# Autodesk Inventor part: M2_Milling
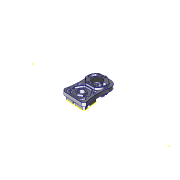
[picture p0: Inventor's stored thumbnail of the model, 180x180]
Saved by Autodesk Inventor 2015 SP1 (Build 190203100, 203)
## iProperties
Created: 2015-04
Part Number: M2_Milling
Material: Aço
Document SubType Name: Modeling
Designer: Andrew Almeida
Density: 7.85 g/cm^3
Appearance: Placa
Title: C:/Users/Andrew Almeida/Documents/Projeto WS2015/WS2015 CAD Data ANLAS/07/#07 - CNC Milling/01 - 3D Models/M2_Milling.stp
Creation Date: 2015-04-23
Sending System: Autodesk Translation Framework v4.0.0.5211
Preprocessor: ST-DEVELOPER v16.1
Author: Andrew Almeida
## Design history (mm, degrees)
node "M2_Milling1"
feature "Rosca1" dims "d0" = 10, "d1" = 0
feature "Rosca2" dims "d2" = 10, "d3" = 0
feature "Rosca3" dims "d4" = 10, "d5" = 0
feature "Rosca4" dims "d6" = 10, "d7" = 0
feature "Rosca5" dims "d8" = 10, "d9" = 0
feature "Rosca6" dims "d10" = 10, "d11" = 0
feature "Rosca7" dims "d12" = 20, "d13" = 0
feature "Rosca8" dims "d14" = 10, "d15" = 0
feature "Rosca9" dims "d16" = 10, "d17" = 0
feature "Rosca10" dims "d18" = 10, "d19" = 0
sketch "Esboço2"
  geometry: L1 (4.188, 0)-(4.188, 22); L2 (4.188, 22)-(3.447, 22); L3 (3.447, 22)-(3.447, 0); L4 (3.447, 0)-(4.188, 0); L5 (0, -10.409)-(0, 54.818) reference
  constraints: 8 end point
revolve "Revolução1" sketch "Esboço2" stored, may be unused: angle "d29" = 0 deg
sketch "Esboço1"
  geometry: L1 (-0.583, -0.051)-(-0.5, -0.051); L2 (0.083, -0.691)-(0, -0.851); L3 (-1, -0.851)-(-1.083, -0.691); L4 (-0.417, -0.051)-(-0.5, 0.109); L5 (-0.5, 0.109)-(-0.583, -0.051); L6 (-1, -0.851)-(-0.917, -0.691); L7 (-0.417, -0.051)-(-0.083, -0.691); L8 (-1.083, -0.691)-(-0.917, -0.691); L9 (0.083, -0.691)-(-0.083, -0.691); L10 (-1, -0.851)-(-1, -0.691); L11 (0, -0.851)-(0, -0.691); L12 (-0.5, 0.109)-(-0.5, 0); L13 (-1, -0.742)-(0, -0.742); L14 (-0.083, -0.691)-(0, -0.851); L15 (-0.917, -0.691)-(-0.583, -0.051); L16 (0, 0)-(0, 0.018); L17 (0, 0.018)-(0, 0); L18 (0, 0)-(0.033, 0); L19 (-0.5, 0)-(-0.5, -0.051); L20 (-0.5, -0.051)-(-0.417, -0.051); A1 r 0.094 centre (-1, -0.648) between (-1.083, -0.691) and (-1, -0.742); A2 r 0.094 centre (-1, -0.648) between (-1, -0.742) and (-0.917, -0.691); A3 r 0.094 centre (0, -0.648) between (-0.083, -0.691) and (0, -0.742); A4 r 0.094 centre (0, -0.648) between (0, -0.742) and (0.083, -0.691); A5 r 0.094 centre (-0.5, -0.094) between (-0.5, 0) and (-0.583, -0.051); A6 r 0.094 centre (-0.5, -0.094) between (-0.417, -0.051) and (-0.5, 0)
  constraints: 40 end point, 12 point on circle, 10 parallel, 8 tangent, 6 centre point, 6 collinear, 2 midpoint, 2 point on line, 1 horizontal, 1 perpendicular, 3 other
  dimensions: "d20" = 55 deg angle of L7 L15 (= d27); "d21" = 0.16008 distance of L4.end L1.end (= 0.160083 x Esboço1_Pitch); "d22" = 0.16008 distance of L2.end L11.end (= 0.160083 x Esboço1_Pitch); "Esboço1_ThreadOffset" = 0 distance between parallel lines of L16 L11; "Esboço1_MajorRadius" = 0.74146 distance from line of L13 L16.start; "d25" = 1 distance from line of L2.end L10 (= Esboço1_Pitch); "Esboço1_MinorRadius" = 0 distance edge to line of A6 L18 (derived)
feature "Espiral1" sketch "Esboço1" pitch "d30" = 1.5015; turns "d32" = 1; dims "d31" = 25, "d33" = 0, angle "d34" = 0 deg, angle "d35" = 0 deg, "d36" = 0, "d37" = 0
sketch "Esboço4"
  geometry: L1 (4.188, 0)-(4.188, 22); L2 (4.188, 22)-(3.447, 22); L3 (3.447, 22)-(3.447, 0); L4 (3.447, 0)-(4.188, 0); L5 (0, -10.409)-(0, 54.818) reference
  constraints: 8 end point
revolve "Revolução2" sketch "Esboço4" stored, may be unused: angle "d47" = 0 deg
sketch "Esboço3"
  geometry: L1 (-0.583, -0.051)-(-0.5, -0.051); L2 (0.083, -0.691)-(0, -0.851); L3 (-1, -0.851)-(-1.083, -0.691); L4 (-0.417, -0.051)-(-0.5, 0.109); L5 (-0.5, 0.109)-(-0.583, -0.051); L6 (-1, -0.851)-(-0.917, -0.691); L7 (-0.417, -0.051)-(-0.083, -0.691); L8 (-1.083, -0.691)-(-0.917, -0.691); L9 (0.083, -0.691)-(-0.083, -0.691); L10 (-1, -0.851)-(-1, -0.691); L11 (0, -0.851)-(0, -0.691); L12 (-0.5, 0.109)-(-0.5, 0); L13 (-1, -0.742)-(0, -0.742); L14 (-0.083, -0.691)-(0, -0.851); L15 (-0.917, -0.691)-(-0.583, -0.051); L16 (0, 0)-(0, 0.018); L17 (0, 0.018)-(0, 0); L18 (0, 0)-(0.033, 0); L19 (-0.5, 0)-(-0.5, -0.051); L20 (-0.5, -0.051)-(-0.417, -0.051); A1 r 0.094 centre (-1, -0.648) between (-1.083, -0.691) and (-1, -0.742); A2 r 0.094 centre (-1, -0.648) between (-1, -0.742) and (-0.917, -0.691); A3 r 0.094 centre (0, -0.648) between (-0.083, -0.691) and (0, -0.742); A4 r 0.094 centre (0, -0.648) between (0, -0.742) and (0.083, -0.691); A5 r 0.094 centre (-0.5, -0.094) between (-0.5, 0) and (-0.583, -0.051); A6 r 0.094 centre (-0.5, -0.094) between (-0.417, -0.051) and (-0.5, 0)
  constraints: 40 end point, 12 point on circle, 10 parallel, 8 tangent, 6 centre point, 6 collinear, 2 midpoint, 2 point on line, 1 horizontal, 1 perpendicular, 3 other
  dimensions: "d38" = 55 deg angle of L7 L15 (= d45); "d39" = 0.16008 distance of L4.end L1.end (= 0.160083 x Esboço3_Pitch); "d40" = 0.16008 distance of L2.end L11.end (= 0.160083 x Esboço3_Pitch); "Esboço3_ThreadOffset" = 0 distance between parallel lines of L16 L11; "Esboço3_MajorRadius" = 0.74146 distance from line of L13 L16.start; "d43" = 1 distance from line of L2.end L10 (= Esboço3_Pitch); "Esboço3_MinorRadius" = 0 distance edge to line of A6 L18 (derived)
feature "Espiral2" sketch "Esboço3" pitch "d48" = 1.5015; turns "d50" = 1; dims "d49" = 25, "d51" = 0, angle "d52" = 0 deg, angle "d53" = 0 deg, "d54" = 0, "d55" = 0
sketch "Esboço6"
  geometry: L1 (4.188, 0)-(4.188, 22); L2 (4.188, 22)-(3.447, 22); L3 (3.447, 22)-(3.447, 0); L4 (3.447, 0)-(4.188, 0); L5 (0, -10.409)-(0, 54.818) reference
  constraints: 8 end point
revolve "Revolução3" sketch "Esboço6" stored, may be unused: angle "d65" = 0 deg
sketch "Esboço5"
  geometry: L1 (-0.583, -0.051)-(-0.5, -0.051); L2 (0.083, -0.691)-(0, -0.851); L3 (-1, -0.851)-(-1.083, -0.691); L4 (-0.417, -0.051)-(-0.5, 0.109); L5 (-0.5, 0.109)-(-0.583, -0.051); L6 (-1, -0.851)-(-0.917, -0.691); L7 (-0.417, -0.051)-(-0.083, -0.691); L8 (-1.083, -0.691)-(-0.917, -0.691); L9 (0.083, -0.691)-(-0.083, -0.691); L10 (-1, -0.851)-(-1, -0.691); L11 (0, -0.851)-(0, -0.691); L12 (-0.5, 0.109)-(-0.5, 0); L13 (-1, -0.742)-(0, -0.742); L14 (-0.083, -0.691)-(0, -0.851); L15 (-0.917, -0.691)-(-0.583, -0.051); L16 (0, 0)-(0, 0.018); L17 (0, 0.018)-(0, 0); L18 (0, 0)-(0.033, 0); L19 (-0.5, 0)-(-0.5, -0.051); L20 (-0.5, -0.051)-(-0.417, -0.051); A1 r 0.094 centre (-1, -0.648) between (-1.083, -0.691) and (-1, -0.742); A2 r 0.094 centre (-1, -0.648) between (-1, -0.742) and (-0.917, -0.691); A3 r 0.094 centre (0, -0.648) between (-0.083, -0.691) and (0, -0.742); A4 r 0.094 centre (0, -0.648) between (0, -0.742) and (0.083, -0.691); A5 r 0.094 centre (-0.5, -0.094) between (-0.5, 0) and (-0.583, -0.051); A6 r 0.094 centre (-0.5, -0.094) between (-0.417, -0.051) and (-0.5, 0)
  constraints: 40 end point, 12 point on circle, 10 parallel, 8 tangent, 6 centre point, 6 collinear, 2 midpoint, 2 point on line, 1 horizontal, 1 perpendicular, 3 other
  dimensions: "d56" = 55 deg angle of L7 L15 (= d63); "d57" = 0.16008 distance of L4.end L1.end (= 0.160083 x Esboço5_Pitch); "d58" = 0.16008 distance of L2.end L11.end (= 0.160083 x Esboço5_Pitch); "Esboço5_ThreadOffset" = 0 distance between parallel lines of L16 L11; "Esboço5_MajorRadius" = 0.74146 distance from line of L13 L16.start; "d61" = 1 distance from line of L2.end L10 (= Esboço5_Pitch); "Esboço5_MinorRadius" = 0 distance edge to line of A6 L18 (derived)
feature "Espiral3" sketch "Esboço5" pitch "d66" = 1.5015; turns "d68" = 1; dims "d67" = 25, "d69" = 0, angle "d70" = 0 deg, angle "d71" = 0 deg, "d72" = 0, "d73" = 0
sketch "Esboço8"
  geometry: L1 (4.188, 0)-(4.188, 22); L2 (4.188, 22)-(3.447, 22); L3 (3.447, 22)-(3.447, 0); L4 (3.447, 0)-(4.188, 0); L5 (0, -10.409)-(0, 54.818) reference
  constraints: 8 end point
revolve "Revolução4" sketch "Esboço8" stored, may be unused: angle "d83" = 0 deg
sketch "Esboço7"
  geometry: L1 (-0.583, -0.051)-(-0.5, -0.051); L2 (0.083, -0.691)-(0, -0.851); L3 (-1, -0.851)-(-1.083, -0.691); L4 (-0.417, -0.051)-(-0.5, 0.109); L5 (-0.5, 0.109)-(-0.583, -0.051); L6 (-1, -0.851)-(-0.917, -0.691); L7 (-0.417, -0.051)-(-0.083, -0.691); L8 (-1.083, -0.691)-(-0.917, -0.691); L9 (0.083, -0.691)-(-0.083, -0.691); L10 (-1, -0.851)-(-1, -0.691); L11 (0, -0.851)-(0, -0.691); L12 (-0.5, 0.109)-(-0.5, 0); L13 (-1, -0.742)-(0, -0.742); L14 (-0.083, -0.691)-(0, -0.851); L15 (-0.917, -0.691)-(-0.583, -0.051); L16 (0, 0)-(0, 0.018); L17 (0, 0.018)-(0, 0); L18 (0, 0)-(0.033, 0); L19 (-0.5, 0)-(-0.5, -0.051); L20 (-0.5, -0.051)-(-0.417, -0.051); A1 r 0.094 centre (-1, -0.648) between (-1.083, -0.691) and (-1, -0.742); A2 r 0.094 centre (-1, -0.648) between (-1, -0.742) and (-0.917, -0.691); A3 r 0.094 centre (0, -0.648) between (-0.083, -0.691) and (0, -0.742); A4 r 0.094 centre (0, -0.648) between (0, -0.742) and (0.083, -0.691); A5 r 0.094 centre (-0.5, -0.094) between (-0.5, 0) and (-0.583, -0.051); A6 r 0.094 centre (-0.5, -0.094) between (-0.417, -0.051) and (-0.5, 0)
  constraints: 40 end point, 12 point on circle, 10 parallel, 8 tangent, 6 centre point, 6 collinear, 2 midpoint, 2 point on line, 1 horizontal, 1 perpendicular, 3 other
  dimensions: "d74" = 55 deg angle of L7 L15 (= d81); "d75" = 0.16008 distance of L4.end L1.end (= 0.160083 x Esboço7_Pitch); "d76" = 0.16008 distance of L2.end L11.end (= 0.160083 x Esboço7_Pitch); "Esboço7_ThreadOffset" = 0 distance between parallel lines of L16 L11; "Esboço7_MajorRadius" = 0.74146 distance from line of L13 L16.start; "d79" = 1 distance from line of L2.end L10 (= Esboço7_Pitch); "Esboço7_MinorRadius" = 0 distance edge to line of A6 L18 (derived)
feature "Espiral4" sketch "Esboço7" pitch "d84" = 1.5015; turns "d86" = 1; dims "d85" = 25, "d87" = 0, angle "d88" = 0 deg, angle "d89" = 0 deg, "d90" = 0, "d91" = 0
sketch "Esboço10"
  geometry: L1 (4.188, 0)-(4.188, 22); L2 (4.188, 22)-(3.447, 22); L3 (3.447, 22)-(3.447, 0); L4 (3.447, 0)-(4.188, 0); L5 (0, -10.409)-(0, 54.818) reference
  constraints: 8 end point
revolve "Revolução5" sketch "Esboço10" stored, may be unused: angle "d101" = 0 deg
sketch "Esboço9"
  geometry: L1 (-0.583, -0.051)-(-0.5, -0.051); L2 (0.083, -0.691)-(0, -0.851); L3 (-1, -0.851)-(-1.083, -0.691); L4 (-0.417, -0.051)-(-0.5, 0.109); L5 (-0.5, 0.109)-(-0.583, -0.051); L6 (-1, -0.851)-(-0.917, -0.691); L7 (-0.417, -0.051)-(-0.083, -0.691); L8 (-1.083, -0.691)-(-0.917, -0.691); L9 (0.083, -0.691)-(-0.083, -0.691); L10 (-1, -0.851)-(-1, -0.691); L11 (0, -0.851)-(0, -0.691); L12 (-0.5, 0.109)-(-0.5, 0); L13 (-1, -0.742)-(0, -0.742); L14 (-0.083, -0.691)-(0, -0.851); L15 (-0.917, -0.691)-(-0.583, -0.051); L16 (0, 0)-(0, 0.018); L17 (0, 0.018)-(0, 0); L18 (0, 0)-(0.033, 0); L19 (-0.5, 0)-(-0.5, -0.051); L20 (-0.5, -0.051)-(-0.417, -0.051); A1 r 0.094 centre (-1, -0.648) between (-1.083, -0.691) and (-1, -0.742); A2 r 0.094 centre (-1, -0.648) between (-1, -0.742) and (-0.917, -0.691); A3 r 0.094 centre (0, -0.648) between (-0.083, -0.691) and (0, -0.742); A4 r 0.094 centre (0, -0.648) between (0, -0.742) and (0.083, -0.691); A5 r 0.094 centre (-0.5, -0.094) between (-0.5, 0) and (-0.583, -0.051); A6 r 0.094 centre (-0.5, -0.094) between (-0.417, -0.051) and (-0.5, 0)
  constraints: 40 end point, 12 point on circle, 10 parallel, 8 tangent, 6 centre point, 6 collinear, 2 midpoint, 2 point on line, 1 horizontal, 1 perpendicular, 3 other
  dimensions: "d92" = 55 deg angle of L7 L15 (= d99); "d93" = 0.16008 distance of L4.end L1.end (= 0.160083 x Esboço9_Pitch); "d94" = 0.16008 distance of L2.end L11.end (= 0.160083 x Esboço9_Pitch); "Esboço9_ThreadOffset" = 0 distance between parallel lines of L16 L11; "Esboço9_MajorRadius" = 0.74146 distance from line of L13 L16.start; "d97" = 1 distance from line of L2.end L10 (= Esboço9_Pitch); "Esboço9_MinorRadius" = 0 distance edge to line of A6 L18 (derived)
feature "Espiral5" sketch "Esboço9" pitch "d102" = 1.5015; turns "d104" = 1; dims "d103" = 25, "d105" = 0, angle "d106" = 0 deg, angle "d107" = 0 deg, "d108" = 0, "d109" = 0
sketch "Esboço12"
  geometry: L1 (4.188, 0)-(4.188, 22); L2 (4.188, 22)-(3.447, 22); L3 (3.447, 22)-(3.447, 0); L4 (3.447, 0)-(4.188, 0); L5 (0, -10.409)-(0, 54.818) reference
  constraints: 8 end point
revolve "Revolução6" sketch "Esboço12" stored, may be unused: angle "d119" = 0 deg
sketch "Esboço11"
  geometry: L1 (-0.583, -0.051)-(-0.5, -0.051); L2 (0.083, -0.691)-(0, -0.851); L3 (-1, -0.851)-(-1.083, -0.691); L4 (-0.417, -0.051)-(-0.5, 0.109); L5 (-0.5, 0.109)-(-0.583, -0.051); L6 (-1, -0.851)-(-0.917, -0.691); L7 (-0.417, -0.051)-(-0.083, -0.691); L8 (-1.083, -0.691)-(-0.917, -0.691); L9 (0.083, -0.691)-(-0.083, -0.691); L10 (-1, -0.851)-(-1, -0.691); L11 (0, -0.851)-(0, -0.691); L12 (-0.5, 0.109)-(-0.5, 0); L13 (-1, -0.742)-(0, -0.742); L14 (-0.083, -0.691)-(0, -0.851); L15 (-0.917, -0.691)-(-0.583, -0.051); L16 (0, 0)-(0, 0.018); L17 (0, 0.018)-(0, 0); L18 (0, 0)-(0.033, 0); L19 (-0.5, 0)-(-0.5, -0.051); L20 (-0.5, -0.051)-(-0.417, -0.051); A1 r 0.094 centre (-1, -0.648) between (-1.083, -0.691) and (-1, -0.742); A2 r 0.094 centre (-1, -0.648) between (-1, -0.742) and (-0.917, -0.691); A3 r 0.094 centre (0, -0.648) between (-0.083, -0.691) and (0, -0.742); A4 r 0.094 centre (0, -0.648) between (0, -0.742) and (0.083, -0.691); A5 r 0.094 centre (-0.5, -0.094) between (-0.5, 0) and (-0.583, -0.051); A6 r 0.094 centre (-0.5, -0.094) between (-0.417, -0.051) and (-0.5, 0)
  constraints: 40 end point, 12 point on circle, 10 parallel, 8 tangent, 6 centre point, 6 collinear, 2 midpoint, 2 point on line, 1 horizontal, 1 perpendicular, 3 other
  dimensions: "d110" = 55 deg angle of L7 L15 (= d117); "d111" = 0.16008 distance of L4.end L1.end (= 0.160083 x Esboço11_Pitch); "d112" = 0.16008 distance of L2.end L11.end (= 0.160083 x Esboço11_Pitch); "Esboço11_ThreadOffset" = 0 distance between parallel lines of L16 L11; "Esboço11_MajorRadius" = 0.74146 distance from line of L13 L16.start; "d115" = 1 distance from line of L2.end L10 (= Esboço11_Pitch); "Esboço11_MinorRadius" = 0 distance edge to line of A6 L18 (derived)
feature "Espiral6" sketch "Esboço11" pitch "d120" = 1.5015; turns "d122" = 1; dims "d121" = 25, "d123" = 0, angle "d124" = 0 deg, angle "d125" = 0 deg, "d126" = 0, "d127" = 0
sketch "Esboço16"
  geometry: L1 (2.518, 0)-(2.518, 17.524); L2 (2.518, 17.524)-(1.776, 17.524); L3 (1.776, 17.524)-(1.776, 0); L4 (1.776, 0)-(2.518, 0); L5 (0, -13.608)-(0, 50.559) reference
  constraints: 8 end point
revolve "Revolução8" sketch "Esboço16" stored, may be unused: angle "d155" = 0 deg
sketch "Esboço15"
  geometry: L1 (-0.583, -0.051)-(-0.5, -0.051); L2 (0.083, -0.691)-(0, -0.851); L3 (-1, -0.851)-(-1.083, -0.691); L4 (-0.417, -0.051)-(-0.5, 0.109); L5 (-0.5, 0.109)-(-0.583, -0.051); L6 (-1, -0.851)-(-0.917, -0.691); L7 (-0.417, -0.051)-(-0.083, -0.691); L8 (-1.083, -0.691)-(-0.917, -0.691); L9 (0.083, -0.691)-(-0.083, -0.691); L10 (-1, -0.851)-(-1, -0.691); L11 (0, -0.851)-(0, -0.691); L12 (-0.5, 0.109)-(-0.5, 0); L13 (-1, -0.742)-(0, -0.742); L14 (-0.083, -0.691)-(0, -0.851); L15 (-0.917, -0.691)-(-0.583, -0.051); L16 (0, 0)-(0, 0.018); L17 (0, 0.018)-(0, 0); L18 (0, 0)-(0.033, 0); L19 (-0.5, 0)-(-0.5, -0.051); L20 (-0.5, -0.051)-(-0.417, -0.051); A1 r 0.094 centre (-1, -0.648) between (-1.083, -0.691) and (-1, -0.742); A2 r 0.094 centre (-1, -0.648) between (-1, -0.742) and (-0.917, -0.691); A3 r 0.094 centre (0, -0.648) between (-0.083, -0.691) and (0, -0.742); A4 r 0.094 centre (0, -0.648) between (0, -0.742) and (0.083, -0.691); A5 r 0.094 centre (-0.5, -0.094) between (-0.5, 0) and (-0.583, -0.051); A6 r 0.094 centre (-0.5, -0.094) between (-0.417, -0.051) and (-0.5, 0)
  constraints: 40 end point, 12 point on circle, 10 parallel, 8 tangent, 6 centre point, 6 collinear, 2 midpoint, 2 point on line, 1 horizontal, 1 perpendicular, 3 other
  dimensions: "d146" = 55 deg angle of L7 L15 (= d153); "d147" = 0.16008 distance of L4.end L1.end (= 0.160083 x Esboço15_Pitch); "d148" = 0.16008 distance of L2.end L11.end (= 0.160083 x Esboço15_Pitch); "Esboço15_ThreadOffset" = 0 distance between parallel lines of L16 L11; "Esboço15_MajorRadius" = 0.74146 distance from line of L13 L16.start; "d151" = 1 distance from line of L2.end L10 (= Esboço15_Pitch); "Esboço15_MinorRadius" = 0 distance edge to line of A6 L18 (derived)
feature "Espiral8" sketch "Esboço15" pitch "d156" = 1.001; turns "d158" = 1; dims "d157" = 19.52355, "d159" = 0, angle "d160" = 0 deg, angle "d161" = 0 deg, "d162" = 0, "d163" = 0
sketch "Esboço18"
  geometry: L1 (2.517, 0)-(2.517, 17.524); L2 (2.517, 17.524)-(1.776, 17.524); L3 (1.776, 17.524)-(1.776, 0); L4 (1.776, 0)-(2.517, 0); L5 (0, -13.608)-(0, 50.559) reference
  constraints: 8 end point
revolve "Revolução9" sketch "Esboço18" stored, may be unused: angle "d173" = 0 deg
sketch "Esboço17"
  geometry: L1 (-0.583, -0.051)-(-0.5, -0.051); L2 (0.083, -0.691)-(0, -0.851); L3 (-1, -0.851)-(-1.083, -0.691); L4 (-0.417, -0.051)-(-0.5, 0.109); L5 (-0.5, 0.109)-(-0.583, -0.051); L6 (-1, -0.851)-(-0.917, -0.691); L7 (-0.417, -0.051)-(-0.083, -0.691); L8 (-1.083, -0.691)-(-0.917, -0.691); L9 (0.083, -0.691)-(-0.083, -0.691); L10 (-1, -0.851)-(-1, -0.691); L11 (0, -0.851)-(0, -0.691); L12 (-0.5, 0.109)-(-0.5, 0); L13 (-1, -0.742)-(0, -0.742); L14 (-0.083, -0.691)-(0, -0.851); L15 (-0.917, -0.691)-(-0.583, -0.051); L16 (0, 0)-(0, 0.018); L17 (0, 0.018)-(0, 0); L18 (0, 0)-(0.033, 0); L19 (-0.5, 0)-(-0.5, -0.051); L20 (-0.5, -0.051)-(-0.417, -0.051); A1 r 0.094 centre (-1, -0.648) between (-1.083, -0.691) and (-1, -0.742); A2 r 0.094 centre (-1, -0.648) between (-1, -0.742) and (-0.917, -0.691); A3 r 0.094 centre (0, -0.648) between (-0.083, -0.691) and (0, -0.742); A4 r 0.094 centre (0, -0.648) between (0, -0.742) and (0.083, -0.691); A5 r 0.094 centre (-0.5, -0.094) between (-0.5, 0) and (-0.583, -0.051); A6 r 0.094 centre (-0.5, -0.094) between (-0.417, -0.051) and (-0.5, 0)
  constraints: 40 end point, 12 point on circle, 10 parallel, 8 tangent, 6 centre point, 6 collinear, 2 midpoint, 2 point on line, 1 horizontal, 1 perpendicular, 3 other
  dimensions: "d164" = 55 deg angle of L7 L15 (= d171); "d165" = 0.16008 distance of L4.end L1.end (= 0.160083 x Esboço17_Pitch); "d166" = 0.16008 distance of L2.end L11.end (= 0.160083 x Esboço17_Pitch); "Esboço17_ThreadOffset" = 0 distance between parallel lines of L16 L11; "Esboço17_MajorRadius" = 0.74146 distance from line of L13 L16.start; "d169" = 1 distance from line of L2.end L10 (= Esboço17_Pitch); "Esboço17_MinorRadius" = 0 distance edge to line of A6 L18 (derived)
feature "Espiral9" sketch "Esboço17" pitch "d174" = 1.001; turns "d176" = 1; dims "d175" = 19.52355, "d177" = 0, angle "d178" = 0 deg, angle "d179" = 0 deg, "d180" = 0, "d181" = 0
sketch "Esboço20"
  geometry: L1 (2.518, 0)-(2.518, 17.524); L2 (2.518, 17.524)-(1.776, 17.524); L3 (1.776, 17.524)-(1.776, 0); L4 (1.776, 0)-(2.518, 0); L5 (0, -13.608)-(0, 50.559) reference
  constraints: 8 end point
revolve "Revolução10" sketch "Esboço20" stored, may be unused: angle "d191" = 0 deg
sketch "Esboço19"
  geometry: L1 (-0.583, -0.051)-(-0.5, -0.051); L2 (0.083, -0.691)-(0, -0.851); L3 (-1, -0.851)-(-1.083, -0.691); L4 (-0.417, -0.051)-(-0.5, 0.109); L5 (-0.5, 0.109)-(-0.583, -0.051); L6 (-1, -0.851)-(-0.917, -0.691); L7 (-0.417, -0.051)-(-0.083, -0.691); L8 (-1.083, -0.691)-(-0.917, -0.691); L9 (0.083, -0.691)-(-0.083, -0.691); L10 (-1, -0.851)-(-1, -0.691); L11 (0, -0.851)-(0, -0.691); L12 (-0.5, 0.109)-(-0.5, 0); L13 (-1, -0.742)-(0, -0.742); L14 (-0.083, -0.691)-(0, -0.851); L15 (-0.917, -0.691)-(-0.583, -0.051); L16 (0, 0)-(0, 0.018); L17 (0, 0.018)-(0, 0); L18 (0, 0)-(0.033, 0); L19 (-0.5, 0)-(-0.5, -0.051); L20 (-0.5, -0.051)-(-0.417, -0.051); A1 r 0.094 centre (-1, -0.648) between (-1.083, -0.691) and (-1, -0.742); A2 r 0.094 centre (-1, -0.648) between (-1, -0.742) and (-0.917, -0.691); A3 r 0.094 centre (0, -0.648) between (-0.083, -0.691) and (0, -0.742); A4 r 0.094 centre (0, -0.648) between (0, -0.742) and (0.083, -0.691); A5 r 0.094 centre (-0.5, -0.094) between (-0.5, 0) and (-0.583, -0.051); A6 r 0.094 centre (-0.5, -0.094) between (-0.417, -0.051) and (-0.5, 0)
  constraints: 40 end point, 12 point on circle, 10 parallel, 8 tangent, 6 centre point, 6 collinear, 2 midpoint, 2 point on line, 1 horizontal, 1 perpendicular, 3 other
  dimensions: "d182" = 55 deg angle of L7 L15 (= d189); "d183" = 0.16008 distance of L4.end L1.end (= 0.160083 x Esboço19_Pitch); "d184" = 0.16008 distance of L2.end L11.end (= 0.160083 x Esboço19_Pitch); "Esboço19_ThreadOffset" = 0 distance between parallel lines of L16 L11; "Esboço19_MajorRadius" = 0.74146 distance from line of L13 L16.start; "d187" = 1 distance from line of L2.end L10 (= Esboço19_Pitch); "Esboço19_MinorRadius" = 0 distance edge to line of A6 L18 (derived)
feature "Espiral10" sketch "Esboço19" pitch "d192" = 1.001; turns "d194" = 1; dims "d193" = 19.52355, "d195" = 0, angle "d196" = 0 deg, angle "d197" = 0 deg, "d198" = 0, "d199" = 0
sketch "Esboço22"
  geometry: L1 (20.263, 0)-(20.263, 20); L2 (20.263, 20)-(19.522, 20); L3 (19.522, 20)-(19.522, 0); L4 (19.522, 0)-(20.263, 0); L5 (0, -10.925)-(0, 53.242) reference
  constraints: 8 end point
revolve "Revolução11" sketch "Esboço22" stored, may be unused: angle "d209" = 0 deg
sketch "Esboço21"
  geometry: L1 (-0.583, -0.051)-(-0.5, -0.051); L2 (0.083, -0.691)-(0, -0.851); L3 (-1, -0.851)-(-1.083, -0.691); L4 (-0.417, -0.051)-(-0.5, 0.109); L5 (-0.5, 0.109)-(-0.583, -0.051); L6 (-1, -0.851)-(-0.917, -0.691); L7 (-0.417, -0.051)-(-0.083, -0.691); L8 (-1.083, -0.691)-(-0.917, -0.691); L9 (0.083, -0.691)-(-0.083, -0.691); L10 (-1, -0.851)-(-1, -0.691); L11 (0, -0.851)-(0, -0.691); L12 (-0.5, 0.109)-(-0.5, 0); L13 (-1, -0.742)-(0, -0.742); L14 (-0.083, -0.691)-(0, -0.851); L15 (-0.917, -0.691)-(-0.583, -0.051); L16 (0, 0)-(0, 0.018); L17 (0, 0.018)-(0, 0); L18 (0, 0)-(0.033, 0); L19 (-0.5, 0)-(-0.5, -0.051); L20 (-0.5, -0.051)-(-0.417, -0.051); A1 r 0.094 centre (-1, -0.648) between (-1.083, -0.691) and (-1, -0.742); A2 r 0.094 centre (-1, -0.648) between (-1, -0.742) and (-0.917, -0.691); A3 r 0.094 centre (0, -0.648) between (-0.083, -0.691) and (0, -0.742); A4 r 0.094 centre (0, -0.648) between (0, -0.742) and (0.083, -0.691); A5 r 0.094 centre (-0.5, -0.094) between (-0.5, 0) and (-0.583, -0.051); A6 r 0.094 centre (-0.5, -0.094) between (-0.417, -0.051) and (-0.5, 0)
  constraints: 40 end point, 12 point on circle, 10 parallel, 8 tangent, 6 centre point, 6 collinear, 2 midpoint, 2 point on line, 1 horizontal, 1 perpendicular, 3 other
  dimensions: "d200" = 55 deg angle of L7 L15 (= d207); "d201" = 0.16008 distance of L4.end L1.end (= 0.160083 x Esboço21_Pitch); "d202" = 0.16008 distance of L2.end L11.end (= 0.160083 x Esboço21_Pitch); "Esboço21_ThreadOffset" = 0 distance between parallel lines of L16 L11; "Esboço21_MajorRadius" = 0.74146 distance from line of L13 L16.start; "d205" = 1 distance from line of L2.end L10 (= Esboço21_Pitch); "Esboço21_MinorRadius" = 0 distance edge to line of A6 L18 (derived)
feature "Espiral11" sketch "Esboço21" pitch "d210" = 1.5015; turns "d212" = 1; dims "d211" = 23, "d213" = 0, angle "d214" = 0 deg, angle "d215" = 0 deg, "d216" = 0, "d217" = 0
sketch "Sketch23"
  geometry: L1 (-36.015, -99)-(-41.972, -93.043) reference; L2 (36.015, -99)-(-36.015, -99) reference; L3 (41.972, -93.043)-(36.015, -99) reference; L4 (-36.843, -101)-(-44.144, -93.699); L5 (44.144, -93.699)-(36.843, -101); L6 (36.843, -101)-(-36.843, -101); A1 r 49.5 centre (0, 0) between (-29.101, -40.042) and (29.101, -40.042) reference; A2 r 5 centre (-32.041, -44.087) between (-29.101, -40.042) and (-37.041, -44.066) reference; A3 r 256 centre (-293.039, -43.031) between (-41.972, -93.043) and (-37.041, -44.066) reference; A4 r 256 centre (293.039, -43.031) between (37.041, -44.066) and (41.972, -93.043) reference; A5 r 5 centre (32.041, -44.087) between (37.041, -44.066) and (29.101, -40.042) reference; A6 r 254 centre (-293.039, -43.031) between (-44.144, -93.699) and (-39.041, -44.058); A7 r 7 centre (-32.041, -44.087) between (-27.926, -38.424) and (-39.041, -44.058); A8 r 47.5 centre (0, 0) between (-27.926, -38.424) and (27.926, -38.424); A9 r 7 centre (32.041, -44.087) between (39.041, -44.058) and (27.926, -38.424); A10 r 254 centre (293.039, -43.031) between (39.041, -44.058) and (44.144, -93.699); 1 further point
  constraints: 10 point on circle, 6 end point, 5 centre point, 7 other
  dimensions: "d218" = 2 distance between parallel lines of L6 L2
node "Body1"
node "Base1"
node "Sólido2"
node "Sólido3"
node "Sólido4"
node "Sólido5"
node "Sólido6"
node "Sólido7"
node "Sólido9"
node "Sólido10"
node "Sólido11"
node "Sólido12"
other parameters: "d27" = 55 deg [user parameter; used in 1 equation term], "Esboço1_Pitch" = 1 [user parameter; used in 3 equation terms], "d45" = 55 deg [user parameter; used in 1 equation term], "Esboço3_Pitch" = 1 [user parameter; used in 3 equation terms], "d63" = 55 deg [user parameter; used in 1 equation term], "Esboço5_Pitch" = 1 [user parameter; used in 3 equation terms], "d81" = 55 deg [user parameter; used in 1 equation term], "Esboço7_Pitch" = 1 [user parameter; used in 3 equation terms], "d99" = 55 deg [user parameter; used in 1 equation term], "Esboço9_Pitch" = 1 [user parameter; used in 3 equation terms], "d117" = 55 deg [user parameter; used in 1 equation term], "Esboço11_Pitch" = 1 [user parameter; used in 3 equation terms], "d135" = 55 deg [user parameter], "Esboço13_Pitch" = 1 [user parameter], "d153" = 55 deg [user parameter; used in 1 equation term], "Esboço15_Pitch" = 1 [user parameter; used in 3 equation terms], "d171" = 55 deg [user parameter; used in 1 equation term], "Esboço17_Pitch" = 1 [user parameter; used in 3 equation terms], "d189" = 55 deg [user parameter; used in 1 equation term], "Esboço19_Pitch" = 1 [user parameter; used in 3 equation terms], "d207" = 55 deg [user parameter; used in 1 equation term], "Esboço21_Pitch" = 1 [user parameter; used in 3 equation terms]
